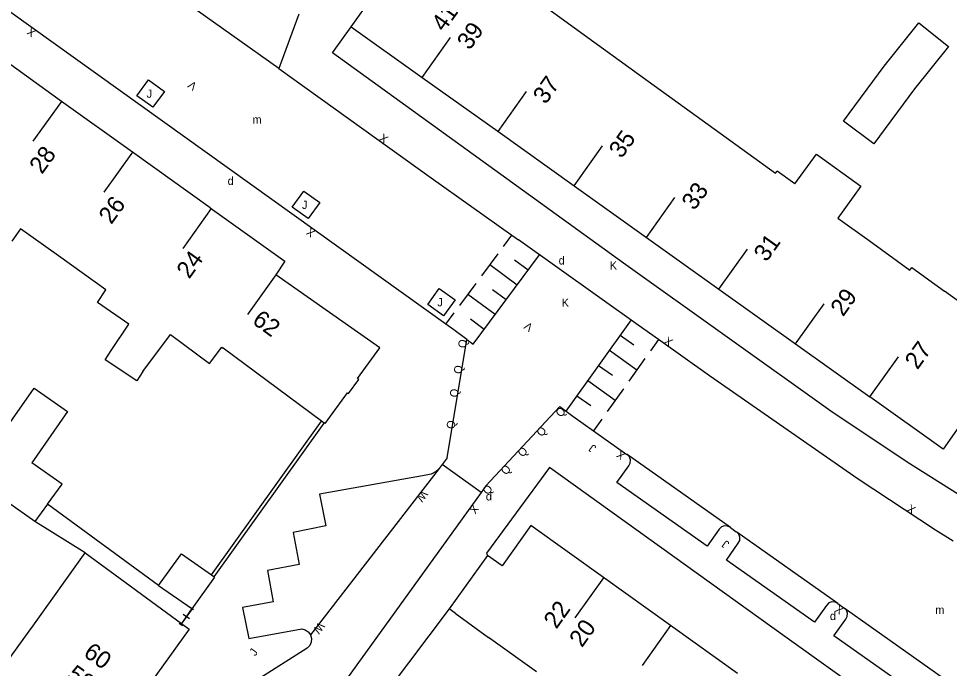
# Model space of a CAD drawing. Extents: x 134999 to 136502, y 457398 to 459002.
# Drawn here: x 135554.4 to 135611.3, y 457486.9 to 457526.7 of the extents above; entities that cross this region are included whole.
import ezdxf

# ---------------------------------------------------------------- set-up
doc = ezdxf.new("R2010")
doc.units = 0
for name, color, linetype in [('RI_DGTB_15', 7, 'Continuous'), ('RI_DGTB_23', 7, 'Continuous'), ('RI_DGTB_29', 7, 'Continuous'), ('RI_DGTB_30', 7, 'Continuous'), ('RI_DGTB_31', 7, 'Continuous'), ('RI_DGTB_35', 7, 'Continuous'), ('RI_DGTB_36', 7, 'Continuous'), ('RI_DGTB_4', 7, 'Continuous'), ('RI_DGTB_43', 7, 'Continuous'), ('RI_DGTB_48', 7, 'Continuous'), ('RI_DGTB_5', 7, 'Continuous'), ('RI_DGTB_53', 7, 'Continuous'), ('RI_DGTB_54', 7, 'Continuous'), ('RI_DGTB_6', 7, 'Continuous')]:
    doc.layers.add(name, color=color, linetype=linetype)

msp = doc.modelspace()

# ---------------------------------------------------------------- linework, layer by layer
at = {"layer": 'RI_DGTB_15'}
for p, q in [((135579.047, 457523.081), (135580.79, 457525.524)), ((135583.692, 457519.768), (135585.435, 457522.211)), ((135556.983, 457521.615), (135555.236, 457519.177)), ((135588.338, 457516.454), (135590.081, 457518.897)), ((135561.323, 457518.506), (135559.576, 457516.068)), ((135592.767, 457513.294), (135594.51, 457515.737)), ((135566.147, 457515.053), (135564.4, 457512.615)), ((135597.204, 457510.127), (135598.947, 457512.57)), ((135570.105, 457511.007), (135568.358, 457508.569)), ((135601.892, 457506.784), (135603.635, 457509.227)), ((135606.442, 457503.538), (135608.185, 457505.981)), ((135590.134, 457492.474), (135588.397, 457490.029)), ((135594.246, 457489.554), (135592.509, 457487.109))]:
    msp.add_line(p, q, dxfattribs=at)
at = {"layer": 'RI_DGTB_23'}
msp.add_line((135564.971, 457490.577), (135564.316, 457489.675), dxfattribs=at)
at = {"layer": 'RI_DGTB_31'}
for p, q in [((135584.034, 457512.745), (135584.543, 457513.429)), ((135582.691, 457510.936), (135583.698, 457512.292)), ((135585.526, 457511.286), (135584.696, 457511.902)), ((135584.855, 457510.381), (135583.195, 457511.614)), ((135581.348, 457509.127), (135582.355, 457510.483)), ((135583.511, 457508.572), (135581.851, 457509.805)), ((135584.183, 457509.477), (135583.353, 457510.093)), ((135580.497, 457507.981), (135581.012, 457508.674)), ((135582.84, 457507.668), (135582.01, 457508.284)), ((135591.825, 457508.247), (135587.845, 457502.655)), ((135591.167, 457507.322), (135592.007, 457506.725)), ((135593.504, 457507.052), (135593.012, 457506.36)), ((135590.506, 457506.393), (135592.185, 457505.198)), ((135592.681, 457505.895), (135591.688, 457504.5)), ((135589.844, 457505.463), (135590.683, 457504.866)), ((135589.182, 457504.533), (135590.861, 457503.338)), ((135591.358, 457504.036), (135590.365, 457502.641)), ((135588.521, 457503.604), (135589.36, 457503.006)), ((135590.034, 457502.176), (135589.528, 457501.465))]:
    msp.add_line(p, q, dxfattribs=at)
for points in [[(135561.6, 457521.948), (135562.299, 457522.924), (135563.275, 457522.225), (135562.576, 457521.249)], [(135571.103, 457515.144), (135571.802, 457516.12), (135572.778, 457515.421), (135572.079, 457514.445)], [(135579.385, 457509.19), (135580.084, 457510.166), (135581.06, 457509.467), (135580.361, 457508.491)]]:
    msp.add_lwpolyline(points, close=True, dxfattribs=at)
msp.add_lwpolyline([(135581.78, 457507.039), (135582.162, 457506.755), (135586.228, 457512.23)], dxfattribs=at)
at = {"layer": 'RI_DGTB_4'}
for p, q in [((135574.705, 457526.179), (135579.328, 457532.642)), ((135574.705, 457526.179), (135579.047, 457523.081)), ((135579.047, 457523.081), (135583.669, 457519.785)), ((135561.323, 457518.506), (135556.983, 457521.615)), ((135583.669, 457519.785), (135588.338, 457516.454)), ((135566.074, 457515.102), (135561.323, 457518.506)), ((135588.338, 457516.454), (135592.767, 457513.294)), ((135592.767, 457513.294), (135597.204, 457510.127)), ((135597.204, 457510.127), (135601.892, 457506.783)), ((135601.892, 457506.783), (135606.442, 457503.537)), ((135558.425, 457493.991), (135564.316, 457489.675)), ((135583.046, 457493.841), (135580.694, 457490.568)), ((135594.242, 457489.549), (135590.14, 457492.483)), ((135598.344, 457486.615), (135594.242, 457489.549))]:
    msp.add_line(p, q, dxfattribs=at)
for points in [[(135556.983, 457521.615), (135552.671, 457524.704), (135552.068, 457523.859)], [(135566.074, 457515.102), (135570.638, 457511.833), (135570.105, 457511.007)], [(135573.11, 457501.901), (135574.475, 457503.787), (135574.54, 457503.741), (135575.167, 457504.608), (135575.102, 457504.654), (135576.463, 457506.532), (135570.105, 457511.007)], [(135615.455, 457506.808), (135610.919, 457500.343), (135606.442, 457503.537)], [(135590.14, 457492.483), (135585.696, 457495.662), (135583.951, 457493.198), (135583.046, 457493.841)], [(135564.316, 457489.675), (135564.784, 457489.332), (135561.66, 457484.96)]]:
    msp.add_lwpolyline(points, dxfattribs=at)
at = {"layer": 'RI_DGTB_48'}
for p, q in [((135564.959, 457490.599), (135564.282, 457489.625)), ((135564.953, 457490.59), (135564.316, 457489.675)), ((135564.426, 457490.247), (135564.815, 457489.977)), ((135564.862, 457490.667), (135565.056, 457490.531)), ((135564.185, 457489.693), (135564.379, 457489.557))]:
    msp.add_line(p, q, dxfattribs=at)
at = {"layer": 'RI_DGTB_5'}
for p, q in [((135586.06, 457527.779), (135588.362, 457526.116)), ((135588.362, 457526.116), (135592.872, 457522.858)), ((135592.872, 457522.858), (135597.282, 457519.674)), ((135597.282, 457519.674), (135600.672, 457517.225)), ((135601.855, 457516.561), (135600.762, 457517.35)), ((135609.004, 457511.444), (135611.006, 457509.998)), ((135613.115, 457508.475), (135611.006, 457509.998)), ((135572.891, 457502.059), (135566.874, 457506.519)), ((135573.061, 457501.936), (135572.891, 457502.059)), ((135573.11, 457501.901), (135573.061, 457501.936)), ((135555.22, 457489.508), (135558.425, 457493.991)), ((135581.06, 457490.305), (135583.115, 457488.83)), ((135553.28, 457486.793), (135555.007, 457489.21)), ((135555.007, 457489.21), (135555.22, 457489.508))]:
    msp.add_line(p, q, dxfattribs=at)
for points in [[(135601.855, 457516.561), (135603.18, 457518.393), (135605.895, 457516.43), (135604.482, 457514.475), (135606.394, 457513.094)], [(135600.672, 457517.225), (135600.762, 457517.35)], [(135556.793, 457512.163), (135554.479, 457513.822), (135553.937, 457513.056)], [(135606.394, 457513.094), (135608.892, 457511.289), (135609.004, 457511.444)], [(135561.105, 457507.985), (135559.181, 457509.301), (135559.7, 457510.08), (135556.793, 457512.163)], [(135560.023, 457506.384), (135561.105, 457507.985)], [(135561.967, 457505.099), (135563.66, 457507.359), (135566.046, 457505.573)], [(135561.967, 457505.099), (135561.589, 457504.527), (135559.645, 457505.812), (135560.023, 457506.384)], [(135566.046, 457505.573), (135566.797, 457506.576), (135566.874, 457506.519)], [(135581.06, 457490.305), (135580.694, 457490.568)], [(135586.048, 457486.723), (135583.115, 457488.83)]]:
    msp.add_lwpolyline(points, dxfattribs=at)
at = {"layer": 'RI_DGTB_53'}
for p, q in [((135591.599, 457500.004), (135591.573, 457500.02)), ((135597.903, 457495.544), (135591.599, 457500.004)), ((135582.659, 457497.682), (135580.276, 457499.405)), ((135580.089, 457499.152), (135572.212, 457488.987)), ((135598.302, 457495.263), (135598.269, 457495.286)), ((135604.477, 457490.897), (135598.302, 457495.263)), ((135604.868, 457490.623), (135604.842, 457490.639)), ((135616.479, 457482.412), (135604.868, 457490.623))]:
    msp.add_line(p, q, dxfattribs=at)
for points in [[(135597.903, 457495.544), (135597.732, 457495.633), (135597.54, 457495.646), (135597.359, 457495.581), (135597.22, 457495.448), (135596.479, 457494.397), (135590.966, 457498.291), (135591.694, 457499.322), (135591.783, 457499.492), (135591.796, 457499.684), (135591.731, 457499.865), (135591.599, 457500.004)], [(135604.477, 457490.897), (135604.307, 457490.987), (135604.116, 457491), (135603.935, 457490.936), (135603.796, 457490.804), (135603.779, 457490.777), (135603.055, 457489.752), (135597.664, 457493.56), (135598.39, 457494.588), (135598.479, 457494.758), (135598.492, 457494.95), (135598.427, 457495.131), (135598.302, 457495.263)], [(135598.302, 457495.263), (135598.295, 457495.27), (135598.269, 457495.286)], [(135616.479, 457482.412), (135616.309, 457482.502), (135616.118, 457482.515), (135615.937, 457482.451), (135615.798, 457482.319), (135615.781, 457482.292), (135615.061, 457481.272), (135604.239, 457488.916), (135604.963, 457489.941), (135605.052, 457490.111), (135605.065, 457490.303), (135605, 457490.484), (135604.868, 457490.623)]]:
    msp.add_lwpolyline(points, dxfattribs=at)
at = {"layer": 'RI_DGTB_54'}
for p, q in [((135570.274, 457523.628), (135564.522, 457527.703)), ((135571.497, 457526.937), (135570.274, 457523.628)), ((135592.267, 457507.932), (135584.944, 457513.144)), ((135566.16, 457492.657), (135572.891, 457502.059)), ((135566.333, 457492.536), (135573.061, 457501.936)), ((135580.276, 457499.405), (135580.089, 457499.152)), ((135580.571, 457499.809), (135580.276, 457499.405)), ((135582.952, 457498.087), (135582.659, 457497.682)), ((135562.914, 457491.994), (135556.128, 457496.97)), ((135558.425, 457493.991), (135555.355, 457495.916)), ((135597.903, 457495.544), (135598.269, 457495.286)), ((135604.477, 457490.897), (135604.842, 457490.639)), ((135580.694, 457490.568), (135576.393, 457484.873))]:
    msp.add_line(p, q, dxfattribs=at)
for points in [[(135580.497, 457507.981), (135547.175, 457531.851)], [(135627.117, 457521.737), (135627.514, 457521.481), (135629.911, 457520.101), (135622.426, 457506.692), (135619.035, 457500.507), (135616.559, 457501.995), (135612.806, 457496.985), (135608.729, 457499.548), (135604.059, 457502.67), (135591.362, 457511.707), (135573.562, 457524.581), (135574.705, 457526.179)], [(135570.274, 457523.628), (135579.605, 457516.943), (135584.543, 457513.429)], [(135584.543, 457513.429), (135584.944, 457513.144)], [(135580.978, 457507.636), (135580.497, 457507.981)], [(135593.504, 457507.052), (135592.267, 457507.932)], [(135581.78, 457507.039), (135580.978, 457507.636)], [(135580.571, 457499.809), (135581.78, 457507.039)], [(135611.528, 457494.722), (135610.457, 457495.384), (135605.73, 457498.501), (135596.621, 457504.834), (135593.504, 457507.052)], [(135582.952, 457498.087), (135587.464, 457502.954)], [(135587.464, 457502.954), (135588.267, 457502.357)], [(135588.267, 457502.357), (135589.528, 457501.465)], [(135589.528, 457501.465), (135591.573, 457500.02)], [(135580.089, 457499.152), (135579.865, 457498.95), (135579.595, 457498.813), (135579.3, 457498.752), (135572.777, 457497.597), (135573.164, 457495.647), (135571.165, 457495.246), (135571.514, 457493.29), (135569.578, 457492.915), (135569.927, 457490.997), (135568.062, 457490.647), (135568.436, 457488.767), (135571.691, 457489.344), (135571.888, 457489.294), (135572.077, 457489.169), (135572.212, 457488.987)], [(135615.046, 457474.668), (135617.087, 457477.543), (135610.341, 457482.383), (135601.229, 457488.886), (135586.835, 457499.225), (135582.976, 457493.98), (135583.046, 457493.841)], [(135582.659, 457497.682), (135572.986, 457484.295), (135569.33, 457481.73), (135569.231, 457481.555)], [(135572.212, 457488.987), (135572.275, 457488.769), (135572.259, 457488.543), (135572.166, 457488.337), (135572.008, 457488.175), (135568.943, 457486.206), (135568.827, 457486.144), (135568.569, 457486.074)]]:
    msp.add_lwpolyline(points, dxfattribs=at)
at = {"layer": 'RI_DGTB_6'}
for p, q in [((135556.128, 457496.97), (135555.355, 457495.916)), ((135566.16, 457492.657), (135566.333, 457492.536)), ((135562.914, 457491.994), (135564.953, 457490.59))]:
    msp.add_line(p, q, dxfattribs=at)
for points in [[(135607.316, 457523.76), (135609.434, 457526.412), (135611.249, 457524.962), (135609.178, 457522.377)], [(135609.178, 457522.377), (135606.686, 457519.022), (135604.824, 457520.405), (135607.316, 457523.76)], [(135553.109, 457500.949), (135555.301, 457504.076), (135557.357, 457502.634), (135555.166, 457499.508)], [(135556.128, 457496.97), (135557.032, 457498.201), (135555.166, 457499.508)], [(135555.355, 457495.916), (135553.533, 457497.195)], [(135562.914, 457491.994), (135564.326, 457493.939), (135566.16, 457492.657)], [(135564.953, 457490.59), (135564.971, 457490.577), (135566.373, 457492.508), (135566.333, 457492.536)]]:
    msp.add_lwpolyline(points, dxfattribs=at)

# ---------------------------------------------------------------- texts
at = {"layer": 'RI_DGTB_29'}
for p in [(135567.147, 457516.498), (135587.399, 457511.635), (135582.943, 457497.201), (135603.995, 457489.887)]:
    msp.add_text('d', height=0.5, dxfattribs=at).set_placement(p)
at = {"layer": 'RI_DGTB_30'}
for s, height, rotation, p in [('X', 0.499, 144.3843, (135555.462, 457525.914)), ('V', 0.499, 144.3878, (135565.313, 457522.646)), ('X', 0.5, 324.6041, (135576.369, 457519.262)), ('X', 0.499, 144.3843, (135572.56, 457513.667)), ('V', 0.499, 144.8024, (135585.873, 457507.897)), ('X', 0.5, 324.6041, (135593.79, 457506.848)), ('X', 0.499, 144.5117, (135591.531, 457500.046)), ('W', 0.499, 233.8246, (135579.029, 457497.863)), ('X', 0.499, 232.4765, (135582.167, 457496.989)), ('X', 0.499, 326.8574, (135608.648, 457496.576)), ('X', 0.499, 144.5117, (135604.902, 457490.598)), ('W', 0.499, 232.4767, (135572.731, 457489.798))]:
    msp.add_text(s, height=height, rotation=rotation, dxfattribs=at).set_placement(p)
for p in [(135590.522, 457511.325), (135587.587, 457509.052)]:
    msp.add_text('K', height=0.5, dxfattribs=at).set_placement(p)
at = {"layer": 'RI_DGTB_31'}
for s, height, rotation, p in [('J', 0.5, 1, (135562.193, 457521.832)), ('J', 0.5, 1, (135571.696, 457515.028)), ('J', 0.5, 1, (135579.978, 457509.074)), ('Q', 0.499, 80.5069, (135581.723, 457506.492)), ('Q', 0.499, 80.5069, (135581.458, 457504.913)), ('Q', 0.499, 80.5069, (135581.212, 457503.48)), ('Q', 0.5, 47.1676, (135587.522, 457502.25)), ('Q', 0.499, 80.5069, (135581.014, 457501.542)), ('Q', 0.5, 47.1676, (135586.348, 457501.061)), ('J', 0.499, 144.5117, (135589.741, 457500.483)), ('Q', 0.5, 47.1676, (135585.195, 457499.816)), ('Q', 0.5, 47.1676, (135584.171, 457498.717)), ('Q', 0.5, 47.1676, (135583.051, 457497.506)), ('J', 0.499, 144.5117, (135597.884, 457494.619)), ('J', 0.499, 54.4415, (135568.837, 457487.65))]:
    msp.add_text(s, height=height, rotation=rotation, dxfattribs=at).set_placement(p)
at = {"layer": 'RI_DGTB_35'}
for s, rotation, p in [('41', 54.497, (135580.386, 457525.818)), ('24', 54.3727, (135564.796, 457510.708)), ('62', 323.9861, (135568.59, 457508.074)), ('27', 54.497, (135609.35, 457505.154)), ('22', 54.6121, (135587.26, 457489.294)), ('60', 324.4462, (135558.266, 457487.727))]:
    msp.add_text(s, height=1.054, rotation=rotation, dxfattribs=at).set_placement(p)
at = {"layer": 'RI_DGTB_36'}
for s, rotation, p in [('39', 54.497, (135581.955, 457524.696)), ('37', 54.497, (135586.6, 457521.383)), ('35', 54.497, (135591.247, 457518.07)), ('28', 54.3727, (135555.787, 457517.109)), ('33', 54.497, (135595.701, 457514.892)), ('26', 54.3727, (135560.032, 457514.042)), ('31', 54.497, (135600.112, 457511.742)), ('29', 54.497, (135604.8, 457508.399)), ('20', 54.6121, (135588.824, 457488.159)), ('58', 324.4462, (135557.244, 457486.361))]:
    msp.add_text(s, height=1.054, rotation=rotation, dxfattribs=at).set_placement(p)
at = {"layer": 'RI_DGTB_43'}
for p in [(135568.668, 457520.252), (135610.442, 457490.26)]:
    msp.add_text('m', height=0.5, dxfattribs=at).set_placement(p)

doc.saveas('drawing.dxf')
